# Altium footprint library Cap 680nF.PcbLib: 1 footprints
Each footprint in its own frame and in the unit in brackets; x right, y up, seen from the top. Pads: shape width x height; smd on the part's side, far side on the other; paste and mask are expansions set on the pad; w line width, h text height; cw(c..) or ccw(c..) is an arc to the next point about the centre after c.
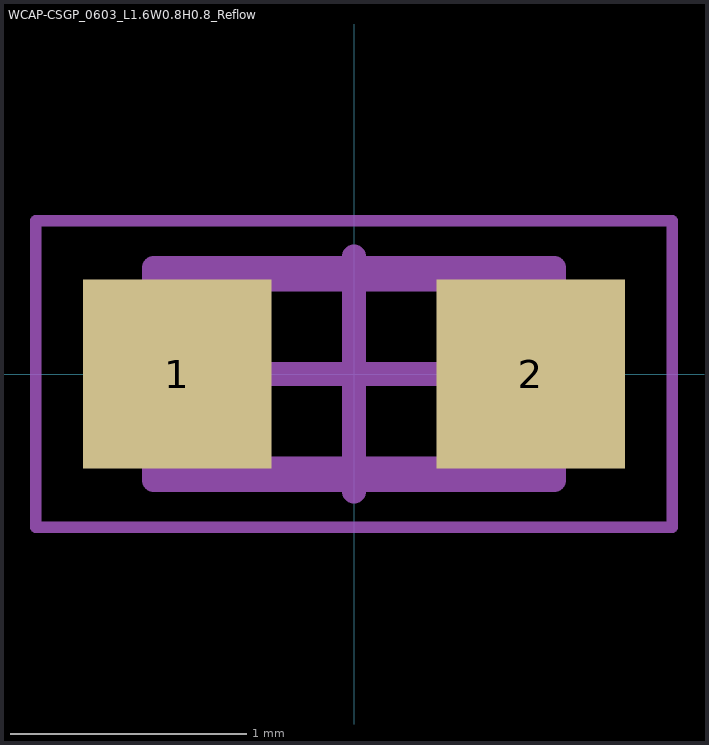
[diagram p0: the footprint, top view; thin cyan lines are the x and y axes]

## WCAP-CSGP_0603_L1.6W0.8H0.8_Reflow [mm] "Ceramic Capacitors, body 1.6x0.8mm"
height 0.8
pads (2):
  rect 0.8x0.8 smd: 1(-0.75,0) 2(0.75,0)
Top Assembly:
  lines w0.1: -0.85,-0.45 0.85,-0.45 0.85,0.45 -0.85,0.45 -0.85,-0.45
Top Designator:
  text ".Designator" at -3.647,-0.357 h1
Top 3D Body:
  lines w0.1: -0.8,-0.4 0.8,-0.4 0.8,0.4 -0.8,0.4 -0.8,-0.4
Top Courtyard:
  lines w0.05: -1.35,-0.65 1.35,-0.65 1.35,0.65 -1.35,0.65 -1.35,-0.65
Top Component Center:
  lines w0.1: -0.5,0 0.5,0 ; 0,-0.5 0,0.5
3D body "CAPC1608X08N.step": height 0.8, standoff 0, extent -0.8,-0.4 0.8,0.4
